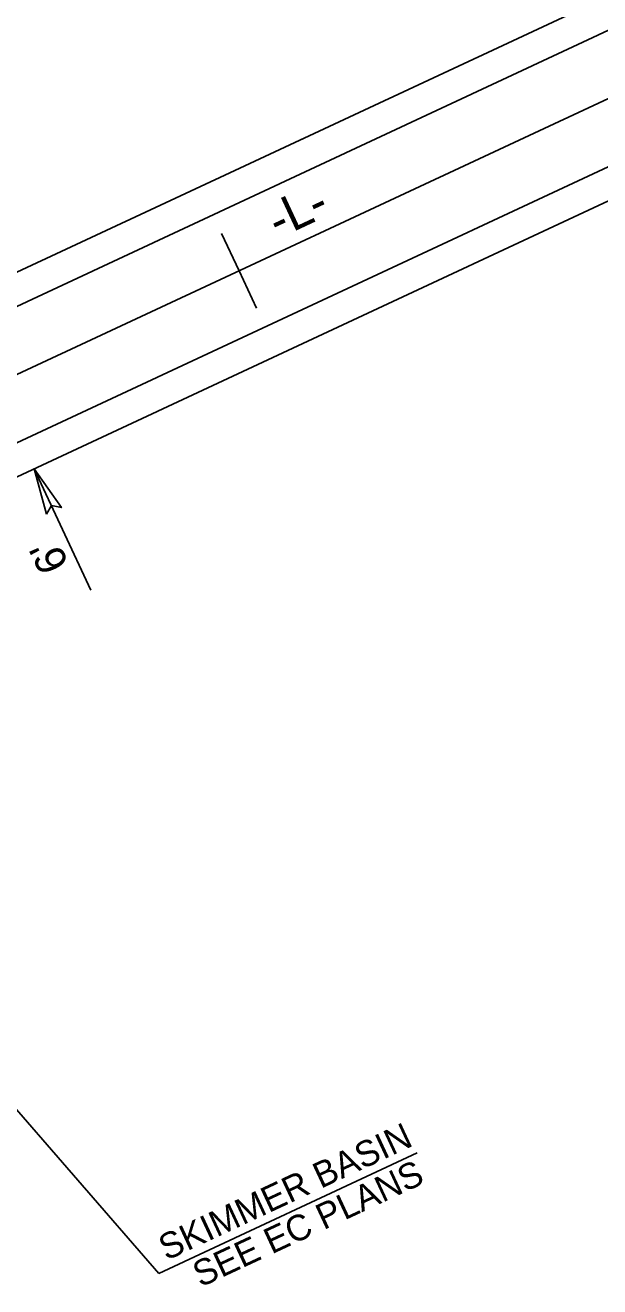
# Model space of a CAD drawing. Extents: x 2320644 to 2322941, y 921672 to 923041.
# Drawn here: x 2321644 to 2321755.6, y 922009.1 to 922253.9 of the extents above; entities that cross this region are included whole.
import ezdxf

# ---------------------------------------------------------------- set-up
doc = ezdxf.new("R2010")
doc.units = 0
for name, color, linetype in [('Matchline', 7, 'Continuous'), ('Prop Approach Slab', 7, 'Continuous'), ('Prop Dimension', 7, 'Continuous'), ('Prop Horizontal Alignment', 7, 'Continuous'), ('Prop Horizontal Alignment Tick Large', 7, 'Continuous'), ('Prop North Arrow NAD83 for Plan Sheets CELL', 7, 'Continuous'), ('Sheet Sticker Exception Certification CELL', 7, 'Continuous')]:
    doc.layers.add(name, color=color, linetype=linetype)

msp = doc.modelspace()

# ---------------------------------------------------------------- linework, layer by layer
at = {"layer": 'Matchline'}
msp.add_line((2321411.13, 922078.36), (2321804.4, 922261.67), dxfattribs=at)
at = {"layer": 'Prop Approach Slab'}
for p, q in [((2321406.06, 922089.24), (2321799.33, 922272.55)), ((2321416.2, 922067.48), (2321809.47, 922250.79))]:
    msp.add_line(p, q, dxfattribs=at)
at = {"layer": 'Prop Horizontal Alignment'}
for q in [(2321682.11, 922213.49), (2321688.87, 922198.99)]:
    msp.add_line((2321685.49, 922206.24), q, dxfattribs=at)
at = {"layer": 'Prop Horizontal Alignment Tick Large'}
for p, q in [((2321592.68, 922182.85), (2321783.02, 922271.57)), ((2321607.89, 922150.22), (2321798.23, 922238.94))]:
    msp.add_line(p, q, dxfattribs=at)
at = {"layer": 'Prop North Arrow NAD83 for Plan Sheets CELL'}
for p, q in [((2321645.71, 922167.84), (2321656.7, 922144.3)), ((2321606.54, 922084.56), (2321669.93, 922011.69)), ((2321669.93, 922011.69), (2321720.13, 922035.09))]:
    msp.add_line(p, q, dxfattribs=at)
at = {"layer": 'Sheet Sticker Exception Certification CELL'}
msp.add_lwpolyline([(2321648.11, 922159.03), (2321645.71, 922167.84), (2321650.99, 922160.32), (2321649.05, 922160.68)], close=True, dxfattribs=at)

# ---------------------------------------------------------------- texts
at = {"layer": 'Prop Dimension'}
msp.add_text('-L-', height=7, rotation=25.0187, dxfattribs=at).set_placement((2321693.08, 922212.42))
at = {"layer": 'Prop North Arrow NAD83 for Plan Sheets CELL'}
for s, height, rotation, p in [("6'", 6, 115.7165, (2321652.57, 922149.31)), ('SKIMMER BASIN', 5, 24.9913, (2321671.4, 922014.11)), ('SEE EC PLANS', 5, 24.9913, (2321678.02, 922008.92))]:
    msp.add_text(s, height=height, rotation=rotation, dxfattribs=at).set_placement(p)

doc.saveas('drawing.dxf')
